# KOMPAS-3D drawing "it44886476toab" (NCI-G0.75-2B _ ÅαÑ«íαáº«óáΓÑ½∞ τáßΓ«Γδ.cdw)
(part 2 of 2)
  Кривая без истории:10764
  Кривая без истории:10765
  Кривая без истории:10766
  Кривая без истории:10767
  Кривая без истории:10768
  Кривая без истории:10769
  Кривая без истории:10770
  Кривая без истории:10771
  Кривая без истории:10772
  Кривая без истории:10773
  Кривая без истории:10774
  Кривая без истории:10775
  Кривая без истории:10776
  Кривая без истории:10777
  Кривая без истории:10778
  Кривая без истории:10779
  Кривая без истории:10780
  Кривая без истории:10781
  Кривая без истории:10782
  Кривая без истории:10783
  Кривая без истории:10784
  Кривая без истории:10785
  Кривая без истории:10786
  Кривая без истории:10787
  Кривая без истории:10788
  Кривая без истории:10789
  Кривая без истории:10790
  Кривая без истории:10791
  Кривая без истории:10792
  Кривая без истории:10793
  Кривая без истории:10794
  Кривая без истории:10795
  Кривая без истории:10796
  Кривая без истории:10797
  Кривая без истории:10798
  Кривая без истории:10799
  Кривая без истории:10800
  Кривая без истории:10801
  Кривая без истории:10802
  Кривая без истории:10803
  Кривая без истории:10804
  Кривая без истории:10805
  Кривая без истории:10806
  Кривая без истории:10807
  Кривая без истории:10808
  Кривая без истории:10809
  Кривая без истории:10810
  Кривая без истории:10811
  Кривая без истории:10812
  Кривая без истории:10813
  Кривая без истории:10814
  Кривая без истории:10815
  Кривая без истории:10816
  Кривая без истории:10817
  Кривая без истории:10818
  Кривая без истории:10819
  Кривая без истории:10820
  Кривая без истории:10821
  Кривая без истории:10822
  Кривая без истории:10823
  Кривая без истории:10824
  Кривая без истории:10825
  Кривая без истории:10826
  Кривая без истории:10827
  Кривая без истории:10828
  Кривая без истории:10829
  Кривая без истории:10830
  Кривая без истории:10831
  Кривая без истории:10832
  Кривая без истории:10833
  Кривая без истории:10834
  Кривая без истории:10835
  Кривая без истории:10836
  Кривая без истории:10837
  Кривая без истории:10838
  Кривая без истории:10839
  Кривая без истории:10840
  Кривая без истории:10841
  Кривая без истории:10842
  Кривая без истории:10843
  Кривая без истории:10844
  Кривая без истории:10845
  Кривая без истории:10846
  Кривая без истории:10847
  Кривая без истории:10848
  Кривая без истории:10849
  Кривая без истории:10850
  Кривая без истории:10851
  Кривая без истории:10852
  Кривая без истории:10853
  Кривая без истории:10854
  Кривая без истории:10855
  Кривая без истории:10856
  Кривая без истории:10857
  Кривая без истории:10858
  Кривая без истории:10859
  Кривая без истории:10860
  Кривая без истории:10861
  Кривая без истории:10862
  Кривая без истории:10863
  Кривая без истории:10864
  Кривая без истории:10865
  Кривая без истории:10866
  Кривая без истории:10867
  Кривая без истории:10868
  Кривая без истории:10869
  Кривая без истории:10870
  Кривая без истории:10871
  Кривая без истории:10872
  Кривая без истории:10873
  Кривая без истории:10874
  Кривая без истории:10875
  Кривая без истории:10876
  Кривая без истории:10877
  Кривая без истории:10878
  Кривая без истории:10879
  Кривая без истории:10880
  Кривая без истории:10881
  Кривая без истории:10882
  Кривая без истории:10883
  Кривая без истории:10884
  Кривая без истории:10885
  Кривая без истории:10886
  Кривая без истории:10887
  Кривая без истории:10888
  Кривая без истории:10889
  Кривая без истории:10890
  Кривая без истории:10891
  Кривая без истории:10892
  Кривая без истории:10893
  Кривая без истории:10894
  Кривая без истории:10895
  Кривая без истории:10896
  Кривая без истории:10897
  Кривая без истории:10898
  Кривая без истории:10899
  Кривая без истории:10900
  Кривая без истории:10901
  Кривая без истории:10902
  Кривая без истории:10903
  Кривая без истории:10904
  Кривая без истории:10905
  Кривая без истории:10906
  Кривая без истории:10907
  Кривая без истории:10908
  Кривая без истории:10909
  Кривая без истории:10910
  Кривая без истории:10911
  Кривая без истории:10912
  Кривая без истории:10913
  Кривая без истории:10914
  Кривая без истории:10915
  Кривая без истории:10916
  Кривая без истории:10917
  Кривая без истории:10918
  Кривая без истории:10919
  Кривая без истории:10920
  Кривая без истории:10921
  Кривая без истории:10922
  Кривая без истории:10923
  Кривая без истории:10924
  Кривая без истории:10925
  Кривая без истории:10926
  Кривая без истории:10927
  Кривая без истории:10928
  Кривая без истории:10929
  Кривая без истории:10930
  Кривая без истории:10931
  Кривая без истории:10932
  Кривая без истории:10933
  Кривая без истории:10934
  Кривая без истории:10935
  Кривая без истории:10936
  Кривая без истории:10937
  Кривая без истории:10938
  Кривая без истории:10939
  Кривая без истории:10940
  Кривая без истории:10941
  Кривая без истории:10942
  Кривая без истории:10943
  Кривая без истории:10944
  Кривая без истории:10945
  Кривая без истории:10946
  Кривая без истории:10947
  Кривая без истории:10948
  Кривая без истории:10949
  Кривая без истории:10950
  Кривая без истории:10951
  Кривая без истории:10952
  Кривая без истории:10953
  Кривая без истории:10954
  Кривая без истории:10955
  Кривая без истории:10956
  Кривая без истории:10957
  Кривая без истории:10958
  Кривая без истории:10959
  Кривая без истории:10960
  Кривая без истории:10961
  Кривая без истории:10962
  Кривая без истории:10963
  Кривая без истории:10964
  Кривая без истории:10965
  Кривая без истории:10966
  Кривая без истории:10967
  Кривая без истории:10968
  Кривая без истории:10969
  Кривая без истории:10970
  Кривая без истории:10971
  Кривая без истории:10972
  Кривая без истории:10973
  Кривая без истории:10974
  Кривая без истории:10975
  Кривая без истории:10976
  Кривая без истории:10977
  Кривая без истории:10978
  Кривая без истории:10979
  Кривая без истории:10980
  Кривая без истории:10981
  Кривая без истории:10982
  Кривая без истории:10983
  Кривая без истории:10984
  Кривая без истории:10985
  Кривая без истории:10986
  Кривая без истории:10987
  Кривая без истории:10988
  Кривая без истории:10989
  Кривая без истории:10990
  Кривая без истории:10991
  Кривая без истории:10992
  Кривая без истории:10993
  Кривая без истории:10994
  Кривая без истории:10995
  Кривая без истории:10996
  Кривая без истории:10997
  Кривая без истории:10998
  Кривая без истории:10999
  Кривая без истории:11000
  Кривая без истории:11001
  Кривая без истории:11002
  Кривая без истории:11003
  Кривая без истории:11004
  Кривая без истории:11005
  Кривая без истории:11006
  Кривая без истории:11007
  Кривая без истории:11008
  Кривая без истории:11009
  Кривая без истории:11010
  Кривая без истории:11011
  Кривая без истории:11012
  Кривая без истории:11013
  Кривая без истории:11014
  Кривая без истории:11015
  Кривая без истории:11016
  Кривая без истории:11017
  Кривая без истории:11018
  Кривая без истории:11019
  Кривая без истории:11020
  Кривая без истории:11021
  Кривая без истории:11022
  Кривая без истории:11023
  Кривая без истории:11024
  Кривая без истории:11025
  Кривая без истории:11026
  Кривая без истории:11027
  Кривая без истории:11028
  Кривая без истории:11029
  Кривая без истории:11030
  Кривая без истории:11031
  Кривая без истории:11032
  Кривая без истории:11033
  Кривая без истории:11034
  Кривая без истории:11035
  Кривая без истории:11036
  Кривая без истории:11037
  Кривая без истории:11038
  Кривая без истории:11039
  Кривая без истории:11040
  Кривая без истории:11041
  Кривая без истории:11042
  Кривая без истории:11043
  Кривая без истории:11044
  Кривая без истории:11045
  Кривая без истории:11046
  Кривая без истории:11047
  Кривая без истории:11048
  Кривая без истории:11049
  Кривая без истории:11050
  Кривая без истории:11051
  Кривая без истории:11052
  Кривая без истории:11053
  Кривая без истории:11054
  Кривая без истории:11055
  Кривая без истории:11056
  Кривая без истории:11057
  Кривая без истории:11058
  Кривая без истории:11059
  Кривая без истории:11060
  Кривая без истории:11061
  Кривая без истории:11062
  Кривая без истории:11063
  Кривая без истории:11064
  Кривая без истории:11065
  Кривая без истории:11066
  Кривая без истории:11067
  Кривая без истории:11068
  Кривая без истории:11069
  Кривая без истории:11070
  Кривая без истории:11071
  Кривая без истории:11072
  Кривая без истории:11073
  Кривая без истории:11074
  Кривая без истории:11075
  Кривая без истории:11076
  Кривая без истории:11077
  Кривая без истории:11078
  Кривая без истории:11079
  Кривая без истории:11080
  Кривая без истории:11081
  Кривая без истории:11082
  Кривая без истории:11083
  Кривая без истории:11084
  Кривая без истории:11085
  Кривая без истории:11086
  Кривая без истории:11087
  Кривая без истории:11088
  Кривая без истории:11089
  Кривая без истории:11090
  Кривая без истории:11091
  Кривая без истории:11092
  Кривая без истории:11093
  Кривая без истории:11094
  Кривая без истории:11095
  Кривая без истории:11096
  Кривая без истории:11097
  Кривая без истории:11098
  Кривая без истории:11099
  Кривая без истории:11100
  Кривая без истории:11101
  Кривая без истории:11102
  Кривая без истории:11103
  Кривая без истории:11104
  Кривая без истории:11105
  Кривая без истории:11106
  Кривая без истории:11107
  Кривая без истории:11108
  Кривая без истории:11109
  Кривая без истории:11110
  Кривая без истории:11111
  Кривая без истории:11112
  Кривая без истории:11113
  Кривая без истории:11114
  Кривая без истории:11115
  Кривая без истории:11116
  Кривая без истории:11117
  Кривая без истории:11118
  Кривая без истории:11119
  Кривая без истории:11120
  Кривая без истории:11121
  Кривая без истории:11122
  Кривая без истории:11123
  Кривая без истории:11124
  Кривая без истории:11125
  Кривая без истории:11126
  Кривая без истории:11127
  Кривая без истории:11128
  Кривая без истории:11129
  Кривая без истории:11130
  Кривая без истории:11131
  Кривая без истории:11132
  Кривая без истории:11133
  Кривая без истории:11134
  Кривая без истории:11135
  Кривая без истории:11136
  Кривая без истории:11137
  Кривая без истории:11138
  Кривая без истории:11139
  Кривая без истории:11140
  Кривая без истории:11141
  Кривая без истории:11142
  Кривая без истории:11143
  Кривая без истории:11144
  Кривая без истории:11145
  Кривая без истории:11146
  Кривая без истории:11147
  Кривая без истории:11148
  Кривая без истории:11149
  Кривая без истории:11150
  Кривая без истории:11151
  Кривая без истории:11152
  Кривая без истории:11153
  Кривая без истории:11154
  Кривая без истории:11155
  Кривая без истории:11156
  Кривая без истории:11157
  Кривая без истории:11158
  Кривая без истории:11159
  Кривая без истории:11160
  Кривая без истории:11161
  Кривая без истории:11162
  Кривая без истории:11163
  Кривая без истории:11164
  Кривая без истории:11165
  Кривая без истории:11166
  Кривая без истории:11167
  Кривая без истории:11168
  Кривая без истории:11169
  Кривая без истории:11170
  Кривая без истории:11171
  Кривая без истории:11172
  Кривая без истории:11173
  Кривая без истории:11174
  Кривая без истории:11175
  Кривая без истории:11176
  Кривая без истории:11177
  Кривая без истории:11178
  Кривая без истории:11179
  Кривая без истории:11180
  Кривая без истории:11181
  Кривая без истории:11182
  Кривая без истории:11183
  Кривая без истории:11184
  Кривая без истории:11185
  Кривая без истории:11186
  Кривая без истории:11187
  Кривая без истории:11188
  Кривая без истории:11189
  Кривая без истории:11190
  Кривая без истории:11191
  Кривая без истории:11192
  Кривая без истории:11193
  Кривая без истории:11194
  Кривая без истории:11195
  Кривая без истории:11196
  Кривая без истории:11197
  Кривая без истории:11198
  Кривая без истории:11199
  Кривая без истории:11200
  Кривая без истории:11201
  Кривая без истории:11202
  Кривая без истории:11203
  Кривая без истории:11204
  Кривая без истории:11205
  Кривая без истории:11206
  Кривая без истории:11207
  Кривая без истории:11208
  Кривая без истории:11209
  Кривая без истории:11210
  Кривая без истории:11211
  Кривая без истории:11212
  Кривая без истории:11213
  Кривая без истории:11214
  Кривая без истории:11215
  Кривая без истории:11216
  Кривая без истории:11217
  Кривая без истории:11218
  Кривая без истории:11219
  Кривая без истории:11220
  Кривая без истории:11221
  Кривая без истории:11222
  Кривая без истории:11223
  Кривая без истории:11224
  Кривая без истории:11225
  Кривая без истории:11226
  Кривая без истории:11227
  Кривая без истории:11228
  Кривая без истории:11229
  Кривая без истории:11230
  Кривая без истории:11231
  Кривая без истории:11232
  Кривая без истории:11233
  Кривая без истории:11234
  Кривая без истории:11235
  Кривая без истории:11236
  Кривая без истории:11237
  Кривая без истории:11238
  Кривая без истории:11239
  Кривая без истории:11240
  Кривая без истории:11241
  Кривая без истории:11242
  Кривая без истории:11243
  Кривая без истории:11244
  Кривая без истории:11245
  Кривая без истории:11246
  Кривая без истории:11247
  Кривая без истории:11248
  Кривая без истории:11249
  Кривая без истории:11250
  Кривая без истории:11251
  Кривая без истории:11252
  Кривая без истории:11253
  Кривая без истории:11254
  Кривая без истории:11255
  Кривая без истории:11256
  Кривая без истории:11257
  Кривая без истории:11258
  Кривая без истории:11259
  Кривая без истории:11260
  Кривая без истории:11261
  Кривая без истории:11262
  Кривая без истории:11263
  Кривая без истории:11264
  Кривая без истории:11265
  Кривая без истории:11266
  Кривая без истории:11267
  Кривая без истории:11268
  Кривая без истории:11269
  Кривая без истории:11270
  Кривая без истории:11271
  Кривая без истории:11272
  Кривая без истории:11273
  Кривая без истории:11274
  Кривая без истории:11275
  Кривая без истории:11276
  Кривая без истории:11277
  Кривая без истории:11278
  Кривая без истории:11279
  Кривая без истории:11280
  Кривая без истории:11281
  Кривая без истории:11282
  Кривая без истории:11283
  Кривая без истории:11284
  Кривая без истории:11285
  Кривая без истории:11286
  Кривая без истории:11287
  Кривая без истории:11288
  Кривая без истории:11289
  Кривая без истории:11290
  Кривая без истории:11291
  Кривая без истории:11292
  Кривая без истории:11293
  Кривая без истории:11294
  Кривая без истории:11295
  Кривая без истории:11296
  Кривая без истории:11297
  Кривая без истории:11298
  Кривая без истории:11299
  Кривая без истории:11300
  Кривая без истории:11301
  Кривая без истории:11302
  Кривая без истории:11303
  Кривая без истории:11304
  Кривая без истории:11305
  Кривая без истории:11306
  Кривая без истории:11307
  Кривая без истории:11308
  Кривая без истории:11309
  Кривая без истории:11310
  Кривая без истории:11311
  Кривая без истории:11312
  Кривая без истории:11313
  Кривая без истории:11314
  Кривая без истории:11315
  Кривая без истории:11316
  Кривая без истории:11317
  Кривая без истории:11318
  Кривая без истории:11319
  Кривая без истории:11320
  Кривая без истории:11321
  Кривая без истории:11322
  Кривая без истории:11323
  Кривая без истории:11324
  Кривая без истории:11325
  Кривая без истории:11326
  Кривая без истории:11327
  Кривая без истории:11328
  Кривая без истории:11329
  Кривая без истории:11330
  Кривая без истории:11331
  Кривая без истории:11332
  Кривая без истории:11333
  Кривая без истории:11334
  Кривая без истории:11335
  Кривая без истории:11336
  Кривая без истории:11337
  Кривая без истории:11338
  Кривая без истории:11339
  Кривая без истории:11340
  Кривая без истории:11341
  Кривая без истории:11342
  Кривая без истории:11343
  Кривая без истории:11344
  Кривая без истории:11345
  Кривая без истории:11346
  Кривая без истории:11347
  Кривая без истории:11348
  Кривая без истории:11349
  Кривая без истории:11350
  Кривая без истории:11351
  Кривая без истории:11352
  Кривая без истории:11353
  Кривая без истории:11354
  Кривая без истории:11355
  Кривая без истории:11356
  Кривая без истории:11357
  Кривая без истории:11358
  Кривая без истории:11359
  Кривая без истории:11360
  Кривая без истории:11361
  Кривая без истории:11362
  Кривая без истории:11363
  Кривая без истории:11364
  Кривая без истории:11365
  Кривая без истории:11366
  Кривая без истории:11367
  Кривая без истории:11368
  Кривая без истории:11369
  Кривая без истории:11370
  Кривая без истории:11371
  Кривая без истории:11372
  Кривая без истории:11373
  Кривая без истории:11374
  Кривая без истории:11375
  Кривая без истории:11376
  Кривая без истории:11377
  Кривая без истории:11378
  Кривая без истории:11379
  Кривая без истории:11380
  Кривая без истории:11381
  Кривая без истории:11382
  Кривая без истории:11383
  Кривая без истории:11384
  Кривая без истории:11385
  Кривая без истории:11386
  Кривая без истории:11387
  Кривая без истории:11388
  Кривая без истории:11389
  Кривая без истории:11390
  Кривая без истории:11391
  Кривая без истории:11392
  Кривая без истории:11393
  Кривая без истории:11394
  Кривая без истории:11395
  Кривая без истории:11396
  Кривая без истории:11397
  Кривая без истории:11398
  Кривая без истории:11399
  Кривая без истории:11400
  Кривая без истории:11401
  Кривая без истории:11402
  Кривая без истории:11403
  Кривая без истории:11404
  Кривая без истории:11405
  Кривая без истории:11406
  Кривая без истории:11407
  Кривая без истории:11408
  Кривая без истории:11409
  Кривая без истории:11410
  Кривая без истории:11411
  Кривая без истории:11412
  Кривая без истории:11413
  Кривая без истории:11414
  Кривая без истории:11415
  Кривая без истории:11416
  Кривая без истории:11417
  Кривая без истории:11418
  Кривая без истории:11419
  Кривая без истории:11420
  Кривая без истории:11421
  Кривая без истории:11422
  Кривая без истории:11423
  Кривая без истории:11424
  Кривая без истории:11425
  Кривая без истории:11426
  Кривая без истории:11427
  Кривая без истории:11428
  Кривая без истории:11429
  Кривая без истории:11430
  Кривая без истории:11431
  Кривая без истории:11432
  Кривая без истории:11433
  Кривая без истории:11434
  Кривая без истории:11435
  Кривая без истории:11436
  Кривая без истории:11437
  Кривая без истории:11438
  Кривая без истории:11439
  Кривая без истории:11440
  Кривая без истории:11441
  Кривая без истории:11442
  Кривая без истории:11443
  Кривая без истории:11444
  Кривая без истории:11445
  Кривая без истории:11446
  Кривая без истории:11447
  Кривая без истории:11448
  Кривая без истории:11449
  Кривая без истории:11450
  Кривая без истории:11451
  Кривая без истории:11452
  Кривая без истории:11453
  Кривая без истории:11454
  Кривая без истории:11455
  Кривая без истории:11456
  Кривая без истории:11457
  Кривая без истории:11458
  Кривая без истории:11459
  Кривая без истории:11460
  Кривая без истории:11461
  Кривая без истории:11462
  Кривая без истории:11463
  Кривая без истории:11464
  Кривая без истории:11465
  Кривая без истории:11466
  Кривая без истории:11467
  Кривая без истории:11468
  Кривая без истории:11469
  Кривая без истории:11470
  Кривая без истории:11471
  Кривая без истории:11472
  Кривая без истории:11473
  Кривая без истории:11474
  Кривая без истории:11475
  Кривая без истории:11476
  Кривая без истории:11477
  Кривая без истории:11478
  Кривая без истории:11479
  Кривая без истории:11480
  Кривая без истории:11481
  Кривая без истории:11482
  Кривая без истории:11483
  Кривая без истории:11484
  Кривая без истории:11485
  Кривая без истории:11486
  Кривая без истории:11487
  Кривая без истории:11488
  Кривая без истории:11489
  Кривая без истории:11490
  Кривая без истории:11491
  Кривая без истории:11492
  Кривая без истории:11493
  Кривая без истории:11494
  Кривая без истории:11495
  Кривая без истории:11496
  Кривая без истории:11497
  Кривая без истории:11498
  Кривая без истории:11499
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Dimensions and other numbers on the sheet: 4±1; 1:1; 1; 13.01.25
